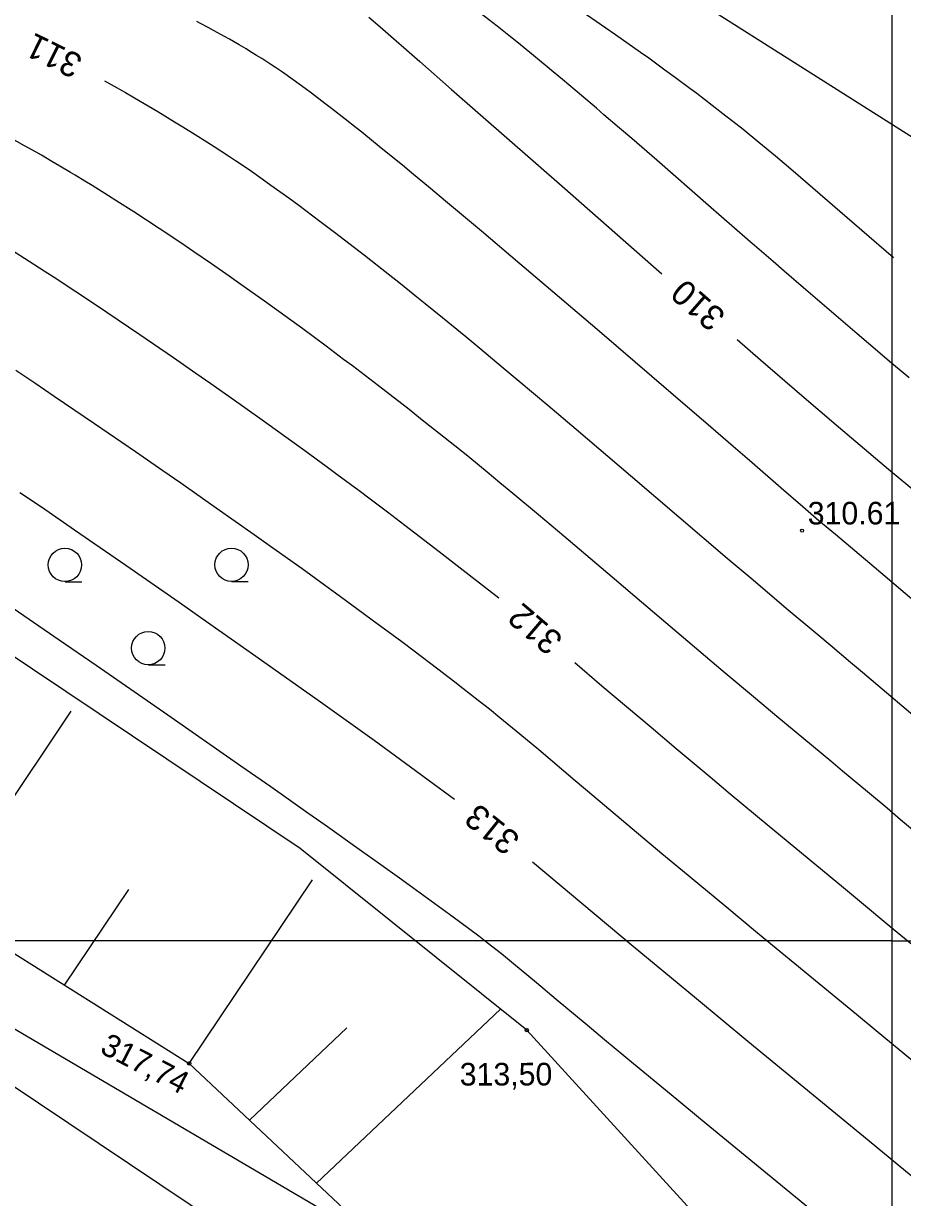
# Model space of a CAD drawing. Extents: x 7477803 to 7478145, y 5500698 to 5500984.
# Drawn here: x 7477973.92 to 7478000.31, y 5500742.3 to 5500777.55 of the extents above; entities that cross this region are included whole.
import ezdxf

# ---------------------------------------------------------------- set-up
doc = ezdxf.new("R2010")
doc.units = 0
for name, color, linetype in [('gr_dzialki', 7, 'Continuous'), ('jezdnia', 7, 'Continuous'), ('pkt_wys', 7, 'Continuous'), ('robocza49', 7, 'Continuous'), ('skarp_wypel', 7, 'Continuous'), ('skarpa_dol', 7, 'Continuous'), ('skarpa_gora', 7, 'Continuous'), ('warst_ciagla', 7, 'Continuous'), ('warst_opis', 7, 'Continuous'), ('warst_pogrub', 7, 'Continuous'), ('warst_przeryw', 7, 'Continuous'), ('zakresy', 7, 'Continuous'), ('zielen', 7, 'Continuous')]:
    doc.layers.add(name, color=color, linetype=linetype)

# ---------------------------------------------------------------- blocks, each defined once
blk = doc.blocks.new('801')
at = {"layer": 'pkt_wys'}
blk.add_circle((0, 0), 0.045, dxfattribs=at)
blk.add_circle((0, 0), 0.045, dxfattribs=at)
blk = doc.blocks.new('941_5')
at = {"layer": 'zielen'}
for p, q in [((-2.5, 0.46), (-2, 0.46)), ((2.5, 0.46), (3, 0.46)), ((0, -2.04), (0.5, -2.04))]:
    blk.add_line(p, q, dxfattribs=at)
for centre in [(-2.503, 0.963), (2.497, 0.963), (-0.003, -1.537)]:
    blk.add_circle(centre, 0.5, dxfattribs=at)
blk = doc.blocks.new('801_5_3')
at = {"layer": 'pkt_wys'}
blk.add_circle((0, 0), 0.05, dxfattribs=at)
blk.add_circle((0, 0), 0.05, dxfattribs=at)

msp = doc.modelspace()

# ---------------------------------------------------------------- linework, layer by layer
at = {"layer": 'gr_dzialki'}
msp.add_lwpolyline([(7477965.87, 5500796.14), (7478019.23, 5500762.35)], dxfattribs=at)
at = {"layer": 'jezdnia'}
msp.add_lwpolyline([(7477992.069, 5500728.595), (7477992.586, 5500729.366), (7477990.061, 5500731.06), (7477991.702, 5500733.507), (7477933.306, 5500772.671), (7477931.61, 5500770.142), (7477929.08, 5500771.838), (7477927.439, 5500769.391), (7477926.244, 5500770.192), (7477925.336, 5500768.842)], dxfattribs=at)
at = {"layer": 'robocza49'}
for p, q in [((7478000, 5500750), (7478000, 5500973.047)), ((7478000, 5500750), (7477937.375, 5500750)), ((7478000, 5500750), (7478063.045, 5500750)), ((7478000, 5500723.706), (7478000, 5500750))]:
    msp.add_line(p, q, dxfattribs=at)
at = {"layer": 'skarp_wypel'}
for p, q in [((7477971.42, 5500751.028), (7477975.36, 5500756.902)), ((7477978.9, 5500746.323), (7477982.596, 5500751.832)), ((7477975.16, 5500748.676), (7477977.088, 5500751.55)), ((7477982.719, 5500742.73), (7477988.242, 5500747.956)), ((7477980.707, 5500744.623), (7477983.632, 5500747.39))]:
    msp.add_line(p, q, dxfattribs=at)
at = {"layer": 'skarpa_dol'}
msp.add_lwpolyline([(7478003.179, 5500722.859), (7478004.323, 5500725.251), (7478005.298, 5500730.032), (7478003.066, 5500732.439), (7477998.881, 5500736.525), (7477989.029, 5500747.324), (7477982.233, 5500752.776), (7477973.187, 5500758.837), (7477956.935, 5500769.599), (7477950.58, 5500774.332), (7477941.825, 5500778.562), (7477933.581, 5500781.953), (7477926.713, 5500780.256), (7477921.899, 5500775.451), (7477920.234, 5500772.903)], dxfattribs=at)
at = {"layer": 'skarpa_gora'}
msp.add_lwpolyline([(7477924.585, 5500769.172), (7477928.36, 5500773.878), (7477930.919, 5500774.6), (7477933.4, 5500774.083), (7477944.537, 5500767.355), (7477948.908, 5500766.44), (7477961.969, 5500756.974), (7477978.9, 5500746.323), (7477991.003, 5500734.936), (7477993.436, 5500731.709), (7477996, 5500728.251), (7477997.928, 5500724.248)], dxfattribs=at)
at = {"layer": 'warst_ciagla'}
for points in [[(7477990.246, 5500778.221), (7477991.693, 5500777.22), (7477992.442, 5500776.695), (7477992.689, 5500776.518), (7477993.016, 5500776.283), (7477993.178, 5500776.166), (7477993.499, 5500775.93), (7477993.923, 5500775.615), (7477994.132, 5500775.457), (7477994.598, 5500775.102), (7477995.007, 5500774.784), (7477995.212, 5500774.624), (7477995.521, 5500774.377), (7477995.996, 5500773.991), (7477996.494, 5500773.578), (7477996.754, 5500773.358), (7477997.025, 5500773.128), (7477997.612, 5500772.623), (7477999.085, 5500771.346), (7478000.039, 5500770.522)], [(7477976.359, 5500775.831), (7477976.558, 5500775.725), (7477976.99, 5500775.479), (7477977.261, 5500775.321), (7477977.959, 5500774.907), (7477978.457, 5500774.605), (7477978.707, 5500774.452), (7477979.074, 5500774.224), (7477979.425, 5500774.003), (7477979.649, 5500773.859), (7477980.08, 5500773.578), (7477980.288, 5500773.439), (7477980.693, 5500773.164), (7477981.09, 5500772.888), (7477981.353, 5500772.702), (7477981.884, 5500772.318), (7477982.19, 5500772.093), (7477982.609, 5500771.781), (7477982.822, 5500771.621), (7477983.258, 5500771.29), (7477983.857, 5500770.83), (7477984.164, 5500770.591), (7477984.873, 5500770.033), (7477985.237, 5500769.743), (7477985.733, 5500769.346), (7477985.985, 5500769.142), (7477986.498, 5500768.726), (7477987.2, 5500768.15), (7477987.558, 5500767.854), (7477988.384, 5500767.167), (7477988.806, 5500766.813), (7477989.66, 5500766.092), (7477990.512, 5500765.367), (7477992.141, 5500763.977), (7477995.045, 5500761.501), (7477995.762, 5500760.892), (7477996.523, 5500760.247), (7477996.82, 5500759.997), (7477997.77, 5500759.204), (7477998.139, 5500758.894), (7477998.751, 5500758.377), (7477999.108, 5500758.074), (7478001.137, 5500756.346)], [(7477988.189, 5500760.298), (7477987.301, 5500760.99), (7477986.404, 5500761.683), (7477985.372, 5500762.474), (7477984.846, 5500762.875), (7477984.331, 5500763.264), (7477983.995, 5500763.516), (7477983.334, 5500764.008), (7477983.009, 5500764.248), (7477982.365, 5500764.72), (7477981.724, 5500765.184), (7477981.297, 5500765.491), (7477980.432, 5500766.107), (7477979.548, 5500766.73), (7477979.1, 5500767.043), (7477978.426, 5500767.511), (7477977.416, 5500768.203), (7477976.424, 5500768.875), (7477975.939, 5500769.2), (7477975.463, 5500769.515), (7477974.845, 5500769.921), (7477974.543, 5500770.117), (7477973.951, 5500770.497), (7477973.191, 5500770.978)], [(7477986.865, 5500754.244), (7477986.075, 5500754.83), (7477985.538, 5500755.224), (7477984.445, 5500756.019), (7477983.891, 5500756.419), (7477982.773, 5500757.219), (7477981.649, 5500758.017), (7477980.901, 5500758.545), (7477979.418, 5500759.586), (7477978.597, 5500760.16), (7477976.994, 5500761.275), (7477975.451, 5500762.342), (7477974.461, 5500763.023), (7477973.819, 5500763.463)], [(7478000.585, 5500749.894), (7477999.932, 5500750.439), (7477999.016, 5500751.199), (7477998.538, 5500751.594), (7477996.244, 5500753.489), (7477995.136, 5500754.411), (7477994.53, 5500754.918), (7477993.515, 5500755.771), (7477992.759, 5500756.408), (7477991.283, 5500757.656), (7477990.469, 5500758.348)], [(7478011.649, 5500734.85), (7478008.326, 5500737.122), (7478007.088, 5500737.967), (7478005.947, 5500738.743), (7478005.498, 5500739.046), (7478004.968, 5500739.4), (7478004.67, 5500739.589), (7478004.599, 5500739.636), (7478004.494, 5500739.711), (7478004.438, 5500739.753), (7478004.348, 5500739.823), (7478004.219, 5500739.926), (7478004.15, 5500739.983), (7478003.614, 5500740.431), (7478002.063, 5500741.714), (7477999.307, 5500743.984), (7477995.668, 5500746.981), (7477994.123, 5500748.258), (7477993.37, 5500748.883), (7477992.227, 5500749.834), (7477990.687, 5500751.121), (7477990, 5500751.698), (7477989.207, 5500752.369)]]:
    msp.add_lwpolyline(points, dxfattribs=at)
at = {"layer": 'warst_pogrub'}
for points in [[(7477984.288, 5500777.748), (7477984.632, 5500777.45), (7477985.817, 5500776.414), (7477986.775, 5500775.576), (7477990.089, 5500772.666), (7477993.082, 5500770.036)], [(7477995.343, 5500768.064), (7477996.048, 5500767.452), (7477997.285, 5500766.385), (7477998.316, 5500765.502), (7477998.904, 5500765.002), (7477999.886, 5500764.173), (7478000.754, 5500763.45)]]:
    msp.add_lwpolyline(points, dxfattribs=at)
at = {"layer": 'warst_przeryw'}
for points in [[(7478001.446, 5500759.531), (7477999.454, 5500761.229), (7477998.295, 5500762.211), (7477997.801, 5500762.622), (7477997.313, 5500763.037), (7477996.665, 5500763.6), (7477995.718, 5500764.425), (7477995.229, 5500764.849), (7477994.407, 5500765.557), (7477993.923, 5500765.974), (7477991.14, 5500768.36), (7477989.612, 5500769.666), (7477988.825, 5500770.337), (7477987.67, 5500771.317), (7477986.593, 5500772.221), (7477986.144, 5500772.595), (7477985.572, 5500773.068), (7477985.298, 5500773.294), (7477984.711, 5500773.773), (7477984.433, 5500773.999), (7477984.077, 5500774.285), (7477983.905, 5500774.422), (7477983.576, 5500774.682), (7477983.165, 5500775.004), (7477982.971, 5500775.153), (7477982.564, 5500775.462), (7477982.375, 5500775.603), (7477982.023, 5500775.859), (7477981.696, 5500776.089), (7477981.486, 5500776.231), (7477981.349, 5500776.322), (7477981.075, 5500776.499), (7477980.92, 5500776.597), (7477980.711, 5500776.726), (7477980.606, 5500776.79), (7477980.394, 5500776.916), (7477980.107, 5500777.082), (7477979.962, 5500777.164), (7477979.632, 5500777.345), (7477979.465, 5500777.435), (7477979.24, 5500777.552), (7477979.126, 5500777.61)], [(7478000.503, 5500766.915), (7477999.922, 5500767.405), (7477999.626, 5500767.655), (7477998.946, 5500768.233), (7477997.892, 5500769.135), (7477997.41, 5500769.55), (7477996.755, 5500770.116), (7477996.422, 5500770.404), (7477995.66, 5500771.067), (7477994.488, 5500772.09), (7477992.93, 5500773.449), (7477992.181, 5500774.099), (7477991.818, 5500774.412), (7477991.348, 5500774.815), (7477991.119, 5500775.011), (7477990.673, 5500775.39), (7477990.102, 5500775.87), (7477989.826, 5500776.1), (7477989.233, 5500776.591), (7477988.734, 5500776.998), (7477988.493, 5500777.192), (7477988.14, 5500777.473), (7477987.626, 5500777.874)], [(7478001.095, 5500752.929), (7478000.252, 5500753.642), (7477999.847, 5500753.984), (7477999.258, 5500754.478), (7477998.511, 5500755.102), (7477998.154, 5500755.399), (7477996.532, 5500756.743), (7477995.893, 5500757.278), (7477994.925, 5500758.091), (7477994.392, 5500758.541), (7477993.532, 5500759.27), (7477992.269, 5500760.342), (7477991.589, 5500760.922), (7477990.139, 5500762.157), (7477989.382, 5500762.797), (7477988.612, 5500763.442), (7477988.225, 5500763.763), (7477987.837, 5500764.083), (7477987.319, 5500764.506), (7477987.059, 5500764.716), (7477986.54, 5500765.134), (7477985.845, 5500765.685), (7477985.497, 5500765.959), (7477984.713, 5500766.568), (7477984.32, 5500766.87), (7477983.796, 5500767.269), (7477983.533, 5500767.467), (7477983.007, 5500767.861), (7477982.304, 5500768.381), (7477981.952, 5500768.639), (7477981.158, 5500769.212), (7477980.451, 5500769.715), (7477980.098, 5500769.964), (7477979.569, 5500770.332), (7477979.042, 5500770.693), (7477978.78, 5500770.872), (7477978.259, 5500771.222), (7477978, 5500771.394), (7477977.615, 5500771.648), (7477977.233, 5500771.897), (7477976.729, 5500772.219), (7477976.479, 5500772.377), (7477975.985, 5500772.685), (7477975.767, 5500772.818), (7477975.479, 5500772.994), (7477975.335, 5500773.08), (7477975.015, 5500773.271), (7477974.776, 5500773.411), (7477974.461, 5500773.595), (7477974.304, 5500773.685), (7477973.954, 5500773.884), (7477973.493, 5500774.14)], [(7478000.605, 5500746.4), (7477999.52, 5500747.297), (7477998.923, 5500747.789), (7477995.956, 5500750.235), (7477994.97, 5500751.051), (7477993.702, 5500752.106), (7477993.088, 5500752.62), (7477992.191, 5500753.372), (7477991.04, 5500754.341), (7477990.485, 5500754.812), (7477989.392, 5500755.737), (7477988.826, 5500756.209), (7477988.225, 5500756.701), (7477987.907, 5500756.957), (7477987.574, 5500757.221), (7477987.109, 5500757.586), (7477986.866, 5500757.775), (7477986.362, 5500758.163), (7477985.65, 5500758.703), (7477985.276, 5500758.983), (7477984.394, 5500759.638), (7477983.931, 5500759.978), (7477983.291, 5500760.445), (7477982.962, 5500760.684), (7477982.284, 5500761.173), (7477981.339, 5500761.848), (7477980.849, 5500762.195), (7477979.706, 5500763.002), (7477978.645, 5500763.744), (7477978.103, 5500764.121), (7477977.282, 5500764.689), (7477976.053, 5500765.535), (7477974.847, 5500766.356), (7477974.263, 5500766.751), (7477973.694, 5500767.134)], [(7477973.325, 5500760.199), (7477974.996, 5500759.047), (7477976.107, 5500758.279), (7477978.254, 5500756.791), (7477980.451, 5500755.261), (7477981.344, 5500754.635), (7477982.458, 5500753.853), (7477982.98, 5500753.484), (7477984.074, 5500752.708), (7477984.579, 5500752.349), (7477985.207, 5500751.899), (7477985.502, 5500751.686), (7477986.054, 5500751.286), (7477986.712, 5500750.805), (7477987.007, 5500750.587), (7477987.589, 5500750.15), (7477987.838, 5500749.959), (7477988.267, 5500749.623), (7477988.635, 5500749.325), (7477988.862, 5500749.136), (7477989.321, 5500748.75), (7477989.909, 5500748.256), (7477990.838, 5500747.481), (7477991.365, 5500747.043), (7477992.231, 5500746.324), (7477993.531, 5500745.249), (7477994.243, 5500744.662), (7477996.537, 5500742.775), (7477997.654, 5500741.857)]]:
    msp.add_lwpolyline(points, dxfattribs=at)
at = {"layer": 'zakresy'}
msp.add_lwpolyline([(7477995.059, 5500962.348), (7477983.951, 5500968.084), (7477970.781, 5500968.613), (7477936.09, 5500958.171), (7477930.511, 5500954.336), (7477914.305, 5500958.58), (7477904.32, 5500957.41), (7477897.265, 5500950.868), (7477811.424, 5500829.338), (7477936.003, 5500769.492), (7478008.982, 5500726.585), (7478019.402, 5500721.781), (7478037.95, 5500734.97), (7478039.493, 5500755.094), (7478043.98, 5500765.708), (7478067.545, 5500795.068), (7478092.109, 5500820.25), (7478076.156, 5500837.989), (7478068.105, 5500851.146), (7478061.422, 5500873.298), (7478054.135, 5500876.371), (7478039.669, 5500897.644), (7478026.36, 5500915.23), (7478015.054, 5500927.728)], close=True, dxfattribs=at)

# ---------------------------------------------------------------- block references
at = {"layer": 'pkt_wys', "rotation": 0.0626175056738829}
for name, p in [('801', (7477997.293, 5500762.323)), ('801_5_3', (7477989.029, 5500747.324)), ('801_5_3', (7477978.9, 5500746.323))]:
    msp.add_blockref(name, p, dxfattribs=at)
at = {"layer": 'zielen', "rotation": 0.0626175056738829}
msp.add_blockref('941_5', (7477977.672, 5500760.332), dxfattribs=at)

# ---------------------------------------------------------------- texts
at = {"layer": 'pkt_wys'}
for s, rotation, p in [('310.61', 0.0626, (7477997.462, 5500762.507)), ('317,74', 332.6797, (7477976.186, 5500746.656)), ('313,50', 0.0626, (7477987.017, 5500745.658))]:
    msp.add_text(s, height=0.68, rotation=rotation, dxfattribs=at).set_placement(p)
at = {"layer": 'warst_opis'}
for s, rotation, p in [('311', 153.7694, (7477975.749, 5500776.55)), ('310', 138.9001, (7477995.042, 5500768.824)), ('312', 139.4632, (7477990.161, 5500759.105)), ('313', 141.3289, (7477988.875, 5500753.116))]:
    msp.add_text(s, height=0.75, rotation=rotation, dxfattribs=at).set_placement(p)

doc.saveas('drawing.dxf')
